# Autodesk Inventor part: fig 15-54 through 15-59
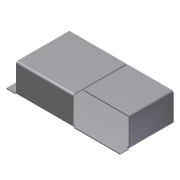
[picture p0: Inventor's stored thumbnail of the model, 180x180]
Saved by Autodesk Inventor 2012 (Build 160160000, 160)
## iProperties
Created: 2008-06
Part Number: fig 15-54 through 15-59
Material: Default
Document SubType Name: Sheet Metal
Designer: CADCIM
Density: 1 g/cm^3
Sheet Metal Rule: Default_mm
Author: CADCIM
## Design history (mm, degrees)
node "Face1"
  sketch "Sketch1"
    geometry: L1 (-32.219, 28.184)-(27.554, 28.184); L2 (27.554, 28.184)-(27.554, 0.063); L3 (27.554, 0.063)-(-32.219, 0.063); L4 (-32.219, 0.063)-(-32.219, 28.184)
    constraints: 8 end point, 2 parallel, 1 horizontal, 1 perpendicular
node "Flange1"
node "Flange2"
node "Flange3"
node "Flange4"
feature "Corner5" dims "d45" = 2 (= CornerReliefSize), "d46" = 0.5 (= BendRadius), "d47" = 0.5 (= Thickness), "d48" = 0, "d49" = 10, "Thickness" = 0.5
body "Solid1"
face "Plate1" dims "Thickness" = 0.5
sketch "Sketch2"
  geometry: L1 (-54.773, 0)-(-24.773, 0); L2 (-24.773, 0)-(-24.773, 15); L3 (-24.773, 15)-(-54.773, 15); L4 (-54.773, 15)-(-54.773, 0)
  constraints: 8 end point
face "Plate2" dims "d1" = 0.5 (= BendReliefWidth), "d2" = 0.25 (= BendReliefDepth), "d3" = 1 (= MinimumRemnant), "d4" = 0.5 (= BendRadius), "d5" = 30, "d6" = 5, "d7" = 15, "d8" = 90 deg, "d9" = 0.5 (= BendRadius), "d10" = 2 (= CornerReliefSize), "d11" = 0.5 (= Thickness), "d12" = 0.5 (= JacobiRadiusSize), "SeamGap" = 0.01, "Thickness" = 0.5
bend "Bend1" dims "d1" = 0.5 (= BendReliefWidth), "d2" = 0.25 (= BendReliefDepth), "d3" = 1 (= MinimumRemnant), "d4" = 0.5 (= BendRadius), "d7" = 15, "d8" = 90 deg, "d9" = 0.5 (= BendRadius), "SeamGap" = 0.01, "Thickness" = 0.5
feature "Corner1" dims "d7" = 15, "d8" = 90 deg, "d10" = 2 (= CornerReliefSize), "d11" = 0.5 (= Thickness), "d12" = 0.5 (= JacobiRadiusSize)
sketch "Sketch3"
  geometry: L1 (0, 15)-(-23.121, 15); L2 (-23.121, 15)-(-23.121, 0); 2 other entities
  constraints: 4 end point, 4 other
face "Plate3" dims "d13" = 0.5 (= BendReliefWidth), "d14" = 0.25 (= BendReliefDepth), "d15" = 1 (= MinimumRemnant), "d16" = 0.5 (= BendRadius), "d17" = 0, "d18" = 5, "d19" = 15, "d20" = 90 deg, "d21" = 0.5 (= BendRadius), "d22" = 2 (= CornerReliefSize), "d23" = 0.5 (= Thickness), "d24" = 0.5 (= JacobiRadiusSize), "SeamGap" = 0.01, "Thickness" = 0.5
bend "Bend2" dims "d13" = 0.5 (= BendReliefWidth), "d14" = 0.25 (= BendReliefDepth), "d15" = 1 (= MinimumRemnant), "d16" = 0.5 (= BendRadius), "d19" = 15, "d20" = 90 deg, "d21" = 0.5 (= BendRadius), "SeamGap" = 0.01, "Thickness" = 0.5
feature "Corner2" dims "d19" = 15, "d20" = 90 deg, "d22" = 2 (= CornerReliefSize), "d23" = 0.5 (= Thickness), "d24" = 0.5 (= JacobiRadiusSize)
sketch "Sketch4"
  geometry: L1 (0, 15)-(-30, 15); L2 (-30, 15)-(-30, 0); 2 other entities
  constraints: 4 end point, 4 other
face "Plate4" dims "d25" = 0.5 (= BendReliefWidth), "d26" = 0.25 (= BendReliefDepth), "d27" = 1 (= MinimumRemnant), "d28" = 0.5 (= BendRadius), "d29" = 15, "d30" = 90 deg, "d31" = 0.5 (= BendRadius), "d32" = 2 (= CornerReliefSize), "d33" = 0.5 (= Thickness), "d34" = 0.5 (= JacobiRadiusSize), "SeamGap" = 0.01, "Thickness" = 0.5
bend "Bend3" dims "d25" = 0.5 (= BendReliefWidth), "d26" = 0.25 (= BendReliefDepth), "d27" = 1 (= MinimumRemnant), "d28" = 0.5 (= BendRadius), "d29" = 15, "d30" = 90 deg, "d31" = 0.5 (= BendRadius), "SeamGap" = 0.01, "Thickness" = 0.5
feature "Corner3" dims "d29" = 15, "d30" = 90 deg, "d32" = 2 (= CornerReliefSize), "d33" = 0.5 (= Thickness), "d34" = 0.5 (= JacobiRadiusSize)
sketch "Sketch5"
  geometry: L1 (15, 0)-(15, 23.121); L2 (15, 23.121)-(0, 23.121); 2 other entities
  constraints: 4 end point, 4 other
face "Plate5" dims "d35" = 0.5 (= BendReliefWidth), "d36" = 0.25 (= BendReliefDepth), "d37" = 1 (= MinimumRemnant), "d38" = 0.5 (= BendRadius), "d39" = 15, "d40" = 90 deg, "d41" = 0.5 (= BendRadius), "d42" = 2 (= CornerReliefSize), "d43" = 0.5 (= Thickness), "d44" = 0.5 (= JacobiRadiusSize), "SeamGap" = 0.01, "Thickness" = 0.5
bend "Bend4" dims "d35" = 0.5 (= BendReliefWidth), "d36" = 0.25 (= BendReliefDepth), "d37" = 1 (= MinimumRemnant), "d38" = 0.5 (= BendRadius), "d39" = 15, "d40" = 90 deg, "d41" = 0.5 (= BendRadius), "SeamGap" = 0.01, "Thickness" = 0.5
feature "Corner4" dims "d39" = 15, "d40" = 90 deg, "d42" = 2 (= CornerReliefSize), "d43" = 0.5 (= Thickness), "d44" = 0.5 (= JacobiRadiusSize)
other parameters: "BendRadius" = 0.5 (= Thickness), "BendReliefWidth" = 0.5 (= Thickness), "BendReliefDepth" = 0.25 (= 0.5 x Thickness), "CornerReliefSize" = 2 (= 4 x Thickness), "MinimumRemnant" = 1 (= 2 x Thickness), "TransitionRadius" = 0.5 (= BendRadius), "JacobiRadiusSize" = 0.5 (= BendRadius), "d0" = 0.5 (= BendRadius), "GapSize" = 0.5 (= Thickness)
